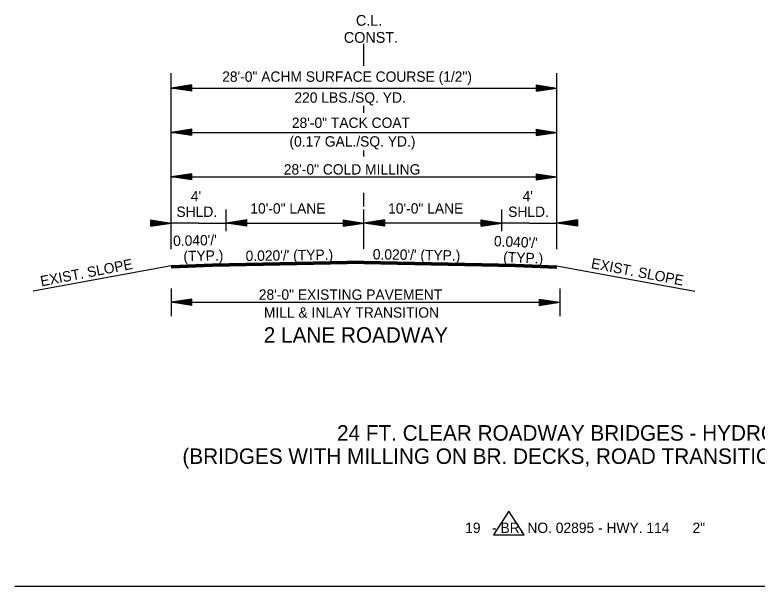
# Model space of a CAD drawing. Extents: x 544199 to 1930787, y -1968972 to 596640.
# Drawn here: x 546318 to 546857, y -1956868 to -1956454 of the extents above; entities that cross this region are included whole.
import ezdxf

# ---------------------------------------------------------------- set-up
doc = ezdxf.new("R2010")
doc.units = 0
doc.layers.add('R_Border', color=7, linetype='Continuous')
doc.layers.add('R_Draft', color=7, linetype='Continuous')

msp = doc.modelspace()

# ---------------------------------------------------------------- linework, layer by layer
at = {"layer": 'R_Border'}
for p, q in [((546461.23, -1956634.36), (546431.23, -1956635.56)), ((546461.23, -1956634.66), (546431.23, -1956635.86)), ((546461.23, -1956634.96), (546431.23, -1956636.16)), ((546461.23, -1956635.26), (546431.23, -1956636.46)), ((546461.23, -1956635.56), (546431.23, -1956636.76)), ((546461.23, -1956635.86), (546431.23, -1956637.06)), ((546461.23, -1956636.03), (546431.23, -1956637.23)), ((546681.23, -1956634.36), (546711.23, -1956635.56)), ((546681.23, -1956634.66), (546711.23, -1956635.86)), ((546681.23, -1956634.96), (546711.23, -1956636.16)), ((546681.23, -1956635.26), (546711.23, -1956636.46)), ((546681.23, -1956635.56), (546711.23, -1956636.76)), ((546681.23, -1956635.86), (546711.23, -1956637.06)), ((546681.23, -1956636.03), (546711.23, -1956637.23)), ((546676.31, -1956813.47), (546665.27, -1956830.77)), ((546687.35, -1956830.77), (546676.31, -1956813.47)), ((546665.27, -1956830.77), (546687.35, -1956830.77)), ((546317.87, -1956867.94), (547239.45, -1956867.94))]:
    msp.add_line(p, q, dxfattribs=at)
at = {"layer": 'R_Draft'}
for p, q in [((546571.23, -1956490.58), (546571.23, -1956474.51)), ((546431.23, -1956623.38), (546431.23, -1956495.9)), ((546711.23, -1956623.38), (546711.23, -1956495.9)), ((546446.23, -1956504.38), (546431.23, -1956506.63)), ((546431.23, -1956506.63), (546711.23, -1956506.63)), ((546446.23, -1956508.88), (546431.23, -1956506.63)), ((546446.23, -1956504.76), (546433.73, -1956506.63)), ((546446.23, -1956508.51), (546433.73, -1956506.63)), ((546446.23, -1956505.14), (546436.31, -1956506.63)), ((546446.23, -1956508.12), (546436.31, -1956506.63)), ((546446.23, -1956505.51), (546438.81, -1956506.63)), ((546446.23, -1956507.75), (546438.81, -1956506.63)), ((546446.23, -1956505.9), (546441.35, -1956506.63)), ((546446.23, -1956507.36), (546441.35, -1956506.63)), ((546446.23, -1956506.28), (546443.86, -1956506.63)), ((546446.23, -1956506.98), (546443.86, -1956506.63)), ((546446.23, -1956508.88), (546446.23, -1956504.38)), ((546696.23, -1956504.38), (546711.23, -1956506.63)), ((546696.23, -1956504.38), (546696.23, -1956508.88)), ((546696.23, -1956504.76), (546708.72, -1956506.63)), ((546696.23, -1956505.14), (546706.14, -1956506.63)), ((546696.23, -1956505.51), (546703.65, -1956506.63)), ((546696.23, -1956505.9), (546701.1, -1956506.63)), ((546696.23, -1956506.28), (546698.6, -1956506.63)), ((546696.23, -1956508.88), (546711.23, -1956506.63)), ((546696.23, -1956507.37), (546701.1, -1956506.63)), ((546696.23, -1956508.12), (546706.14, -1956506.63)), ((546696.23, -1956508.51), (546708.72, -1956506.63)), ((546696.23, -1956507.75), (546703.65, -1956506.63)), ((546696.23, -1956506.98), (546698.6, -1956506.63)), ((546571.23, -1956524.52), (546571.23, -1956519.49)), ((546446.23, -1956536.53), (546431.23, -1956538.78)), ((546431.23, -1956538.78), (546711.23, -1956538.78)), ((546446.23, -1956541.03), (546431.23, -1956538.78)), ((546446.23, -1956536.9), (546433.73, -1956538.78)), ((546446.23, -1956540.65), (546433.73, -1956538.78)), ((546446.23, -1956537.29), (546436.31, -1956538.78)), ((546446.23, -1956540.27), (546436.31, -1956538.78)), ((546446.23, -1956537.66), (546438.81, -1956538.78)), ((546446.23, -1956539.9), (546438.81, -1956538.78)), ((546446.23, -1956538.04), (546441.35, -1956538.78)), ((546446.23, -1956539.51), (546441.35, -1956538.78)), ((546446.23, -1956538.43), (546443.86, -1956538.78)), ((546446.23, -1956539.13), (546443.86, -1956538.78)), ((546446.23, -1956541.03), (546446.23, -1956536.53)), ((546696.23, -1956536.53), (546711.23, -1956538.78)), ((546696.23, -1956536.53), (546696.23, -1956541.03)), ((546696.23, -1956536.9), (546708.72, -1956538.78)), ((546696.23, -1956537.29), (546706.14, -1956538.78)), ((546696.23, -1956537.66), (546703.65, -1956538.78)), ((546696.23, -1956538.05), (546701.1, -1956538.78)), ((546696.23, -1956538.43), (546698.6, -1956538.78)), ((546696.23, -1956541.03), (546711.23, -1956538.78)), ((546696.23, -1956539.51), (546701.1, -1956538.78)), ((546696.23, -1956540.27), (546706.14, -1956538.78)), ((546696.23, -1956540.65), (546708.72, -1956538.78)), ((546696.23, -1956539.9), (546703.65, -1956538.78)), ((546696.23, -1956539.13), (546698.6, -1956538.78)), ((546571.23, -1956556.37), (546571.23, -1956551.91)), ((546446.23, -1956568.77), (546431.23, -1956571.02)), ((546431.23, -1956571.02), (546711.23, -1956571.02)), ((546446.23, -1956573.27), (546431.23, -1956571.02)), ((546446.23, -1956569.14), (546433.73, -1956571.02)), ((546446.23, -1956572.89), (546433.73, -1956571.02)), ((546446.23, -1956569.53), (546436.31, -1956571.02)), ((546446.23, -1956572.51), (546436.31, -1956571.02)), ((546446.23, -1956569.9), (546438.81, -1956571.02)), ((546446.23, -1956572.14), (546438.81, -1956571.02)), ((546446.23, -1956570.28), (546441.35, -1956571.02)), ((546446.23, -1956571.75), (546441.35, -1956571.02)), ((546446.23, -1956570.67), (546443.86, -1956571.02)), ((546446.23, -1956571.37), (546443.86, -1956571.02)), ((546446.23, -1956573.27), (546446.23, -1956568.77)), ((546696.23, -1956568.77), (546711.23, -1956571.02)), ((546696.23, -1956568.77), (546696.23, -1956573.27)), ((546696.23, -1956569.14), (546708.72, -1956571.02)), ((546696.23, -1956569.53), (546706.14, -1956571.02)), ((546696.23, -1956569.9), (546703.65, -1956571.02)), ((546696.23, -1956570.29), (546701.1, -1956571.02)), ((546696.23, -1956570.67), (546698.6, -1956571.02)), ((546696.23, -1956573.27), (546711.23, -1956571.02)), ((546696.23, -1956571.75), (546701.1, -1956571.02)), ((546696.23, -1956572.51), (546706.14, -1956571.02)), ((546696.23, -1956572.89), (546708.72, -1956571.02)), ((546696.23, -1956572.14), (546703.65, -1956571.02)), ((546696.23, -1956571.37), (546698.6, -1956571.02)), ((546571.23, -1956584.55), (546571.23, -1956582.67)), ((546571.23, -1956592.54), (546571.23, -1956584.55)), ((546471.23, -1956610.43), (546471.23, -1956594.66)), ((546571.23, -1956623.21), (546571.23, -1956594.66)), ((546671.23, -1956610.43), (546671.23, -1956594.66)), ((546416.23, -1956602.31), (546431.23, -1956604.56)), ((546416.23, -1956602.31), (546416.23, -1956606.81)), ((546416.23, -1956602.68), (546428.72, -1956604.56)), ((546416.23, -1956603.06), (546426.14, -1956604.56)), ((546416.23, -1956603.44), (546423.65, -1956604.56)), ((546416.23, -1956603.83), (546421.1, -1956604.56)), ((546416.23, -1956604.2), (546418.6, -1956604.56)), ((546416.23, -1956606.81), (546431.23, -1956604.56)), ((546416.23, -1956605.29), (546421.1, -1956604.56)), ((546416.23, -1956606.05), (546426.14, -1956604.56)), ((546416.23, -1956606.43), (546428.72, -1956604.56)), ((546416.23, -1956605.67), (546423.65, -1956604.56)), ((546416.23, -1956604.91), (546418.6, -1956604.56)), ((546451.23, -1956604.56), (546431.23, -1956604.56)), ((546451.23, -1956604.56), (546571.23, -1956604.56)), ((546486.23, -1956602.31), (546471.23, -1956604.56)), ((546486.23, -1956606.81), (546471.23, -1956604.56)), ((546486.23, -1956602.68), (546473.73, -1956604.56)), ((546486.23, -1956606.43), (546473.73, -1956604.56)), ((546486.23, -1956603.06), (546476.31, -1956604.56)), ((546486.23, -1956606.05), (546476.31, -1956604.56)), ((546486.23, -1956603.44), (546478.81, -1956604.56)), ((546486.23, -1956605.67), (546478.81, -1956604.56)), ((546486.23, -1956603.82), (546481.35, -1956604.56)), ((546486.23, -1956605.28), (546481.35, -1956604.56)), ((546486.23, -1956604.2), (546483.86, -1956604.56)), ((546486.23, -1956604.91), (546483.86, -1956604.56)), ((546486.23, -1956606.81), (546486.23, -1956602.31)), ((546556.23, -1956602.31), (546571.23, -1956604.56)), ((546556.23, -1956602.31), (546556.23, -1956606.81)), ((546556.23, -1956602.68), (546568.72, -1956604.56)), ((546556.23, -1956603.06), (546566.14, -1956604.56)), ((546556.23, -1956603.44), (546563.65, -1956604.56)), ((546556.23, -1956603.83), (546561.1, -1956604.56)), ((546556.23, -1956604.2), (546558.6, -1956604.56)), ((546556.23, -1956606.81), (546571.23, -1956604.56)), ((546556.23, -1956605.29), (546561.1, -1956604.56)), ((546556.23, -1956606.05), (546566.14, -1956604.56)), ((546556.23, -1956606.43), (546568.72, -1956604.56)), ((546556.23, -1956605.67), (546563.65, -1956604.56)), ((546556.23, -1956604.91), (546558.6, -1956604.56)), ((546586.23, -1956602.31), (546571.23, -1956604.56)), ((546691.23, -1956604.56), (546571.23, -1956604.56)), ((546586.23, -1956606.81), (546571.23, -1956604.56)), ((546586.23, -1956602.68), (546573.73, -1956604.56)), ((546586.23, -1956606.43), (546573.73, -1956604.56)), ((546586.23, -1956603.06), (546576.31, -1956604.56)), ((546586.23, -1956606.05), (546576.31, -1956604.56)), ((546586.23, -1956603.44), (546578.81, -1956604.56)), ((546586.23, -1956605.67), (546578.81, -1956604.56)), ((546586.23, -1956603.83), (546581.35, -1956604.56)), ((546586.23, -1956605.29), (546581.35, -1956604.56)), ((546586.23, -1956604.2), (546583.86, -1956604.56)), ((546586.23, -1956604.91), (546583.86, -1956604.56)), ((546586.23, -1956602.31), (546586.23, -1956606.81)), ((546656.23, -1956602.31), (546671.23, -1956604.56)), ((546656.23, -1956606.81), (546656.23, -1956602.31)), ((546656.23, -1956602.68), (546668.72, -1956604.56)), ((546656.23, -1956603.06), (546666.14, -1956604.56)), ((546656.23, -1956603.44), (546663.65, -1956604.56)), ((546656.23, -1956603.82), (546661.1, -1956604.56)), ((546656.23, -1956604.2), (546658.6, -1956604.56)), ((546656.23, -1956606.81), (546671.23, -1956604.56)), ((546656.23, -1956605.28), (546661.1, -1956604.56)), ((546656.23, -1956606.05), (546666.14, -1956604.56)), ((546656.23, -1956606.43), (546668.72, -1956604.56)), ((546656.23, -1956605.67), (546663.65, -1956604.56)), ((546656.23, -1956604.91), (546658.6, -1956604.56)), ((546691.23, -1956604.56), (546711.23, -1956604.56)), ((546726.23, -1956602.31), (546711.23, -1956604.56)), ((546726.23, -1956606.81), (546711.23, -1956604.56)), ((546726.23, -1956602.68), (546713.73, -1956604.56)), ((546726.23, -1956606.43), (546713.73, -1956604.56)), ((546726.23, -1956603.06), (546716.31, -1956604.56)), ((546726.23, -1956606.05), (546716.31, -1956604.56)), ((546726.23, -1956603.44), (546718.81, -1956604.56)), ((546726.23, -1956605.67), (546718.81, -1956604.56)), ((546726.23, -1956603.83), (546721.35, -1956604.56)), ((546726.23, -1956605.29), (546721.35, -1956604.56)), ((546726.23, -1956604.2), (546723.86, -1956604.56)), ((546726.23, -1956604.91), (546723.86, -1956604.56)), ((546726.23, -1956602.31), (546726.23, -1956606.81)), ((546571.23, -1956632.16), (546461.23, -1956634.36)), ((546571.23, -1956632.16), (546681.23, -1956634.36)), ((546431.23, -1956635.56), (546331.16, -1956653.94)), ((546571.22, -1956632.46), (546461.23, -1956634.66)), ((546571.23, -1956632.76), (546461.23, -1956634.96)), ((546571.25, -1956633.06), (546461.23, -1956635.26)), ((546571.25, -1956633.36), (546461.23, -1956635.56)), ((546571.26, -1956633.66), (546461.23, -1956635.86)), ((546571.26, -1956633.83), (546461.23, -1956636.03)), ((546571.2, -1956633.36), (546681.23, -1956635.56)), ((546571.2, -1956633.66), (546681.23, -1956635.86)), ((546571.2, -1956633.83), (546681.23, -1956636.03)), ((546571.21, -1956633.06), (546681.23, -1956635.26)), ((546571.22, -1956632.46), (546681.23, -1956634.66)), ((546571.22, -1956632.76), (546681.23, -1956634.96)), ((546711.23, -1956635.56), (546811.3, -1956653.94)), ((546431.23, -1956652.02), (546431.23, -1956672.02)), ((546713.23, -1956652.02), (546713.23, -1956672.02)), ((546446.23, -1956659.77), (546431.23, -1956662.02)), ((546431.23, -1956662.02), (546711.23, -1956662.02)), ((546446.23, -1956664.27), (546431.23, -1956662.02)), ((546446.23, -1956660.14), (546433.73, -1956662.02)), ((546446.23, -1956663.89), (546433.73, -1956662.02)), ((546446.23, -1956660.53), (546436.31, -1956662.02)), ((546446.23, -1956663.51), (546436.31, -1956662.02)), ((546446.23, -1956660.9), (546438.81, -1956662.02)), ((546446.23, -1956663.14), (546438.81, -1956662.02)), ((546446.23, -1956661.28), (546441.35, -1956662.02)), ((546446.23, -1956662.75), (546441.35, -1956662.02)), ((546446.23, -1956661.67), (546443.86, -1956662.02)), ((546446.23, -1956662.37), (546443.86, -1956662.02)), ((546446.23, -1956664.27), (546446.23, -1956659.77)), ((546698.23, -1956659.77), (546713.23, -1956662.02)), ((546698.23, -1956659.77), (546698.23, -1956664.27)), ((546698.23, -1956660.14), (546710.72, -1956662.02)), ((546698.23, -1956660.53), (546708.14, -1956662.02)), ((546698.23, -1956660.9), (546705.65, -1956662.02)), ((546698.23, -1956661.29), (546703.1, -1956662.02)), ((546698.23, -1956661.67), (546700.6, -1956662.02)), ((546698.23, -1956664.27), (546713.23, -1956662.02)), ((546698.23, -1956662.75), (546703.1, -1956662.02)), ((546698.23, -1956663.51), (546708.14, -1956662.02)), ((546698.23, -1956663.89), (546710.72, -1956662.02)), ((546698.23, -1956663.14), (546705.65, -1956662.02)), ((546698.23, -1956662.37), (546700.6, -1956662.02))]:
    msp.add_line(p, q, dxfattribs=at)

# ---------------------------------------------------------------- texts
for s, height, p in [('C.L.', 7.8, (546565.38, -1956461.42)), ('CONST.', 7.8, (546556.6, -1956473.78)), ('28\'-0" ACHM SURFACE COURSE (1/2")', 7.5, (546468.33, -1956502.06)), ('220 LBS./SQ. YD. ', 7.5, (546520.74, -1956517.24)), ('28\'-0" TACK COAT', 7.5, (546518.88, -1956535.53)), ('(0.17 GAL./SQ. YD.)', 7.5, (546517.14, -1956549.07)), ('28\'-0" COLD MILLING', 7.5, (546513.03, -1956569.35)), ("4' ", 7.5, (546445.59, -1956588.83)), ("4' ", 7.5, (546686.3, -1956588.83)), ('SHLD.', 7.5, (546435.14, -1956600.08)), ('10\'-0" LANE', 7.5, (546488.75, -1956597.69)), ('10\'-0" LANE', 7.5, (546588.75, -1956597.69)), ('SHLD.', 7.5, (546675.85, -1956600.08)), ('28\'-0" EXISTING PAVEMENT', 7.5, (546494.9, -1956660.19)), ('MILL & INLAY TRANSITION', 7.5, (546498.62, -1956673.19)), ('2 LANE ROADWAY', 11.25, (546498.5, -1956691.36)), ('24 FT. CLEAR ROADWAY BRIDGES - HYDRODEMOLITION', 11.25, (546551.65, -1956762.41)), ('(BRIDGES WITH MILLING ON BR. DECKS, ROAD TRANSITIONS, AND NEW GUARDRAIL)', 11.25, (546439.46, -1956779.28)), ('      19   - BR. NO. 02895 - HWY. 114      2"', 7.5, (546627.92, -1956829.37))]:
    msp.add_text(s, height=height, dxfattribs=at).set_placement(p)
for s, rotation, p in [("0.040'/' ", 1.3184, (546432.81, -1956621.23)), ("0.040'/' ", 357.6456, (546665.41, -1956621.3)), ('(TYP.)', 1.3184, (546440.27, -1956632.31)), ("0.020'/' (TYP.)", 0.8719, (546485.4, -1956632.12)), ("0.020'/' (TYP.)", 359.1281, (546577.6, -1956630.89)), ('(TYP.)', 357.6456, (546672.15, -1956632.84)), ('EXIST. SLOPE', 10.8829, (546337.14, -1956650.56)), ('EXIST. SLOPE', 349.1171, (546735.61, -1956637.16))]:
    msp.add_text(s, height=7.5, rotation=rotation, dxfattribs=at).set_placement(p)

doc.saveas('drawing.dxf')
